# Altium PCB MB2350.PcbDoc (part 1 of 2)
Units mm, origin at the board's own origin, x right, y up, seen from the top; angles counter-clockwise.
Board outline 43 x 52.78 mm, 4 copper layers (Top Layer, Internal 1, Internal 2, Bottom Layer), stack 1.565 mm thick; 87 components, 78 nets, 331 pads, 863 vias.
Unrouted connection lines stored in the file: 482.
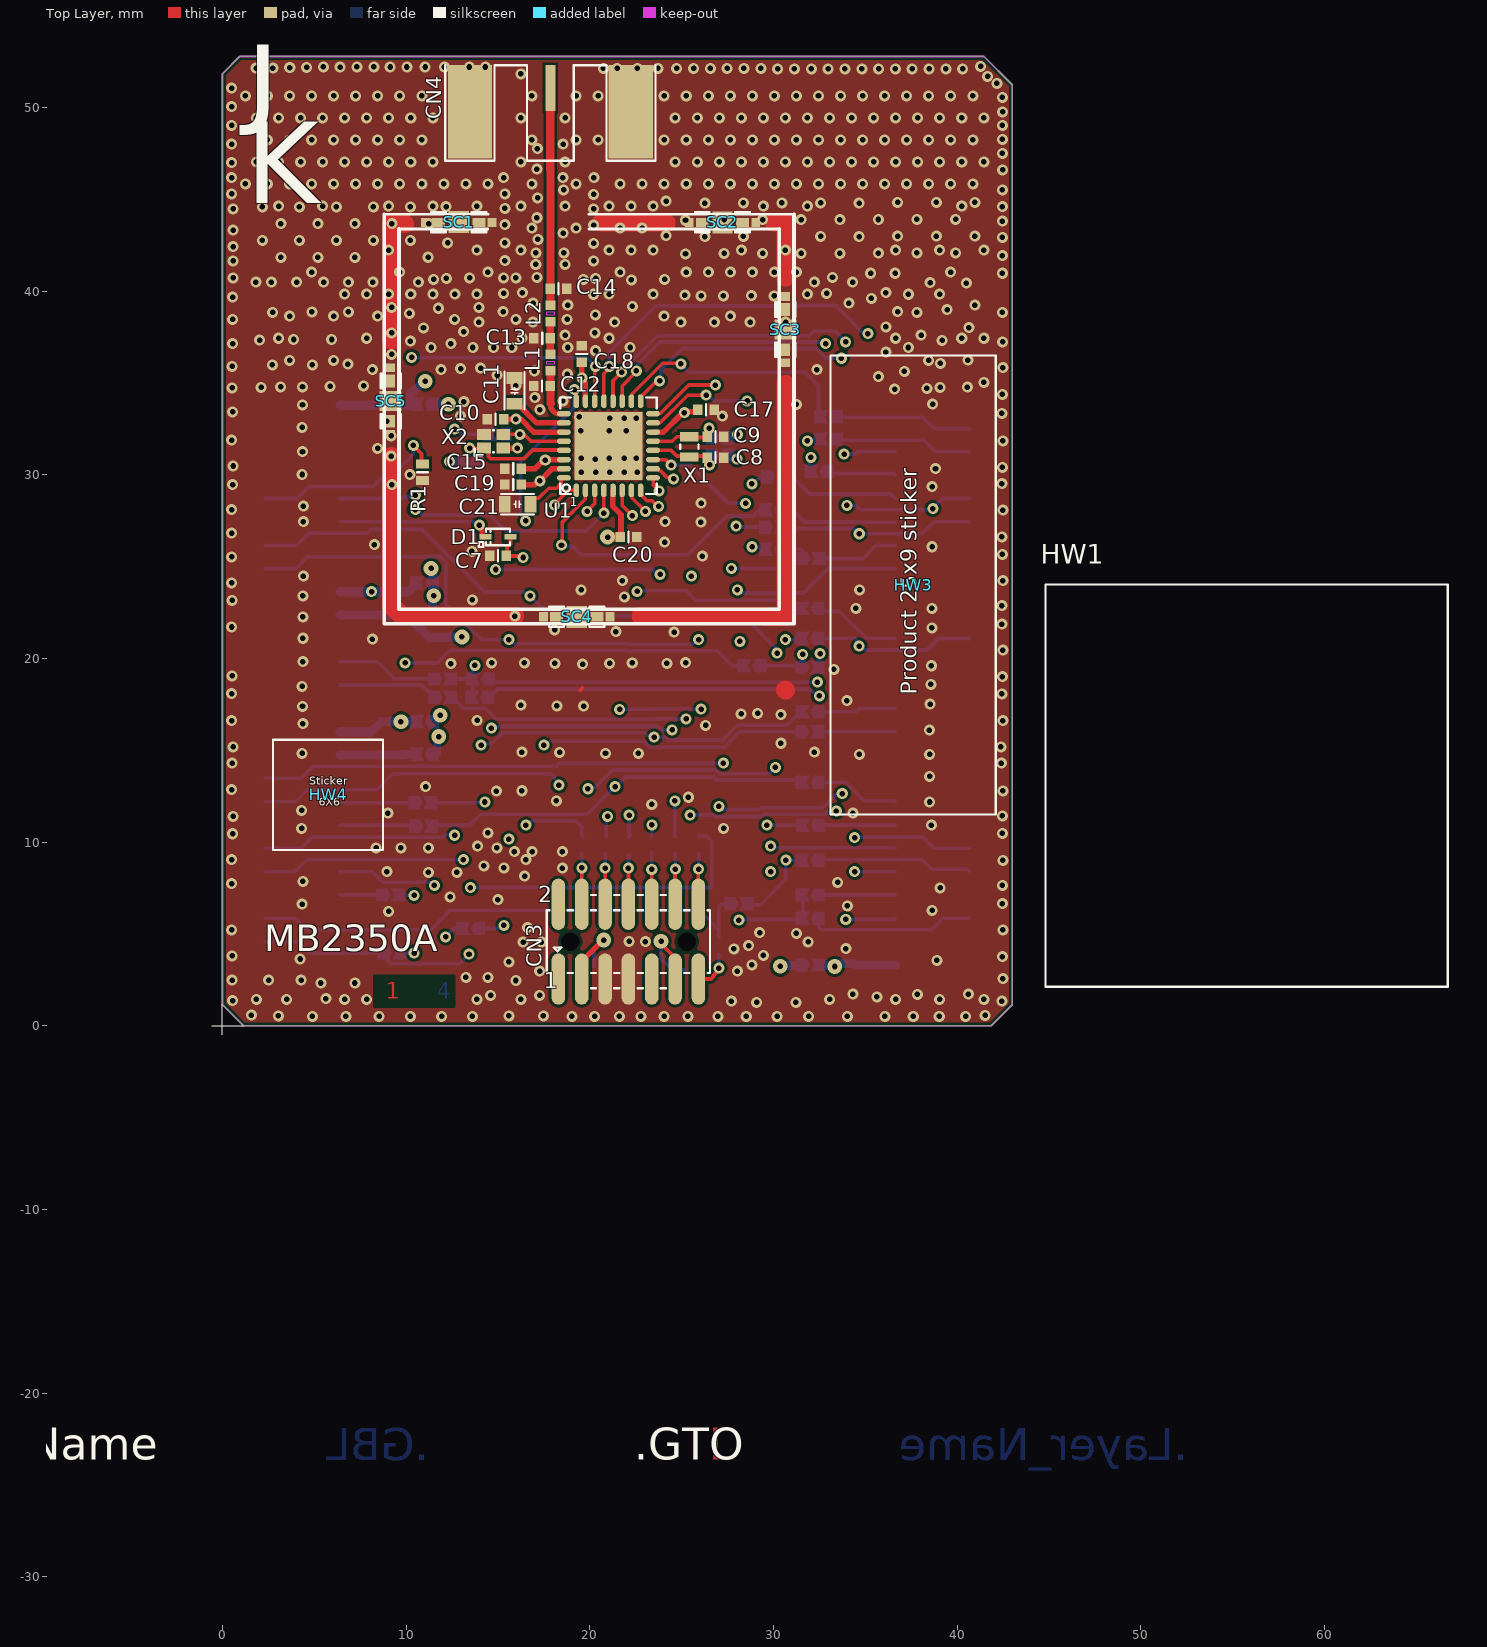
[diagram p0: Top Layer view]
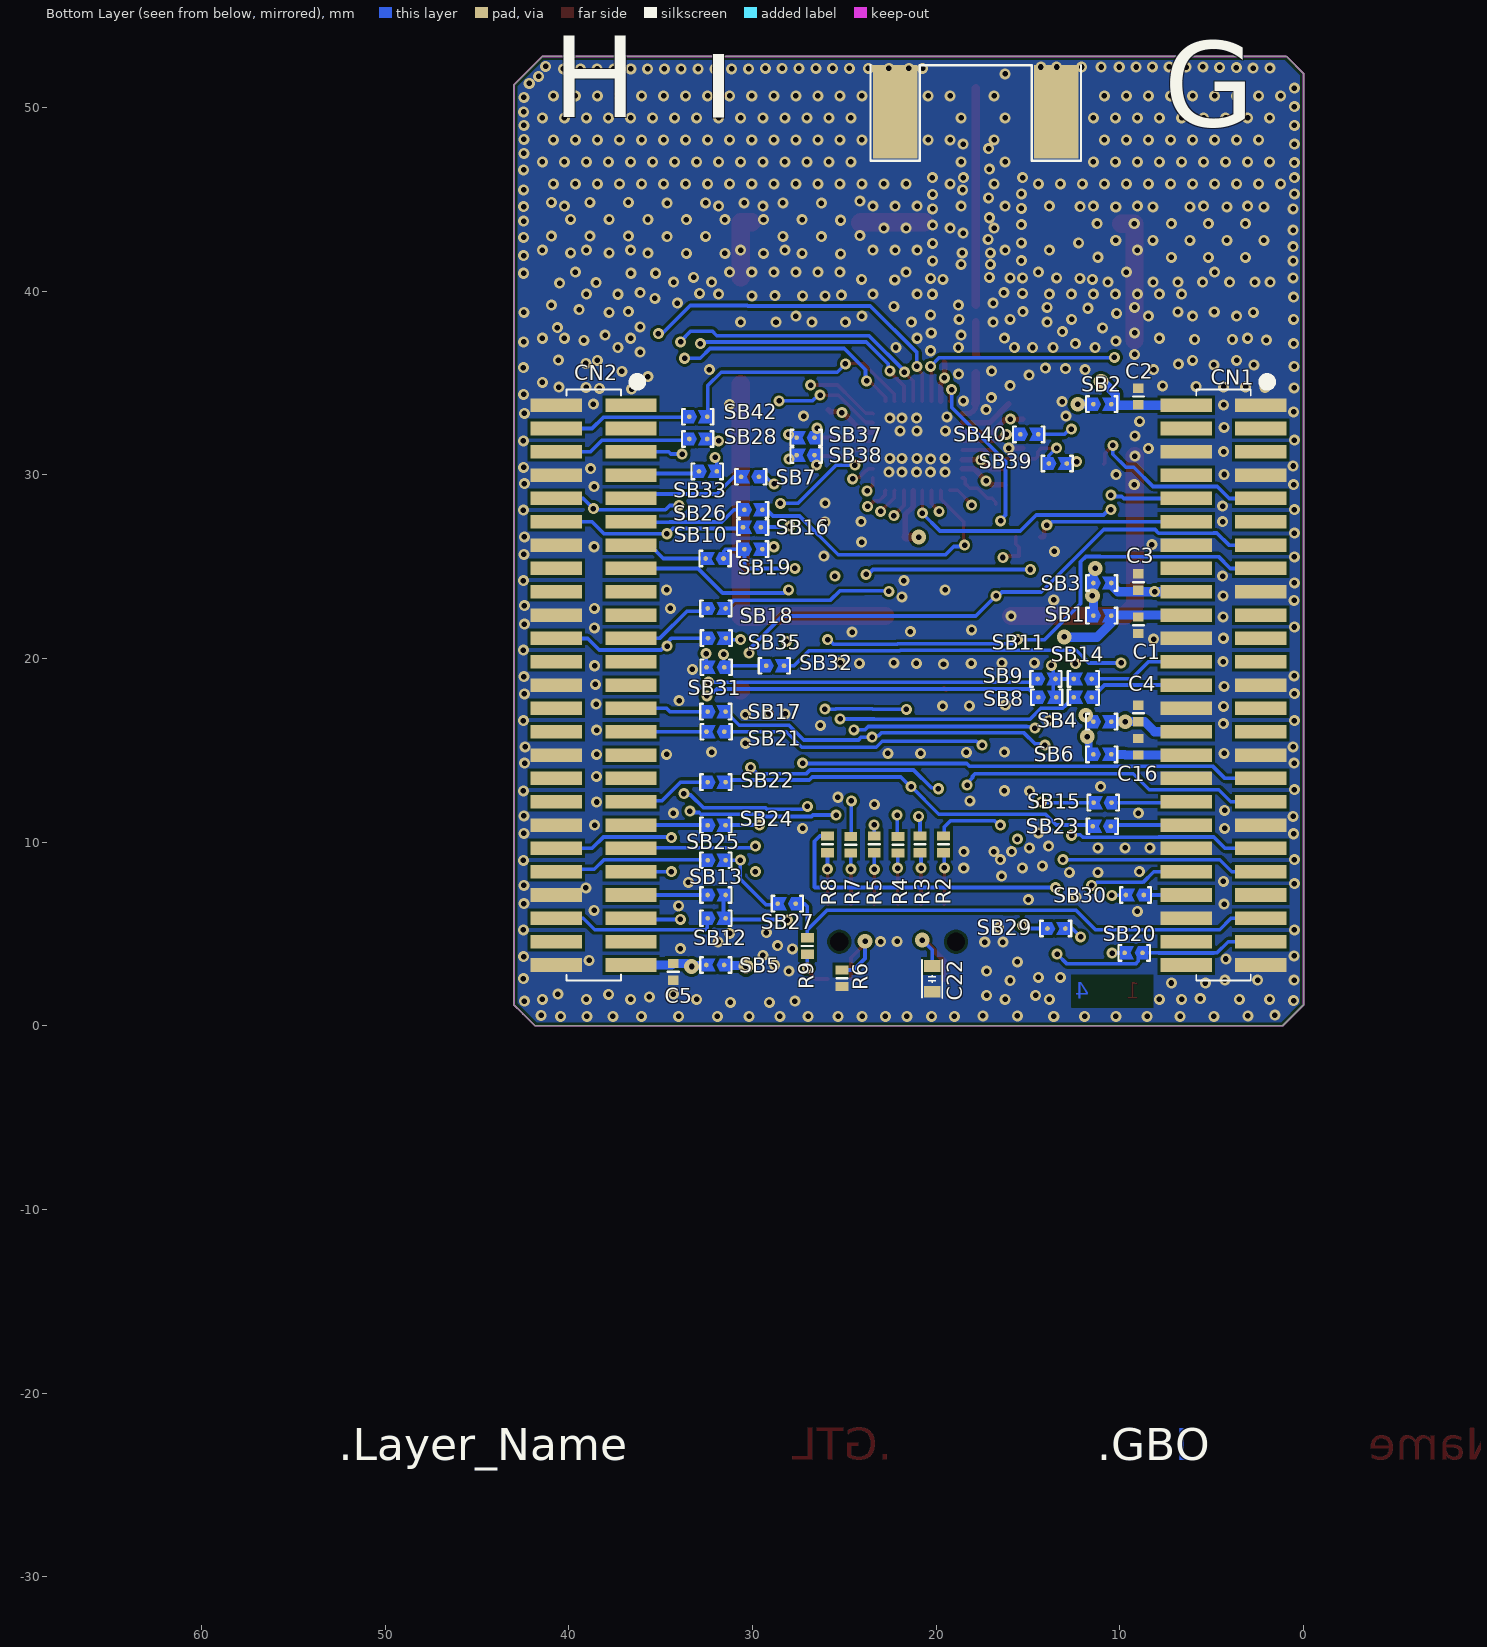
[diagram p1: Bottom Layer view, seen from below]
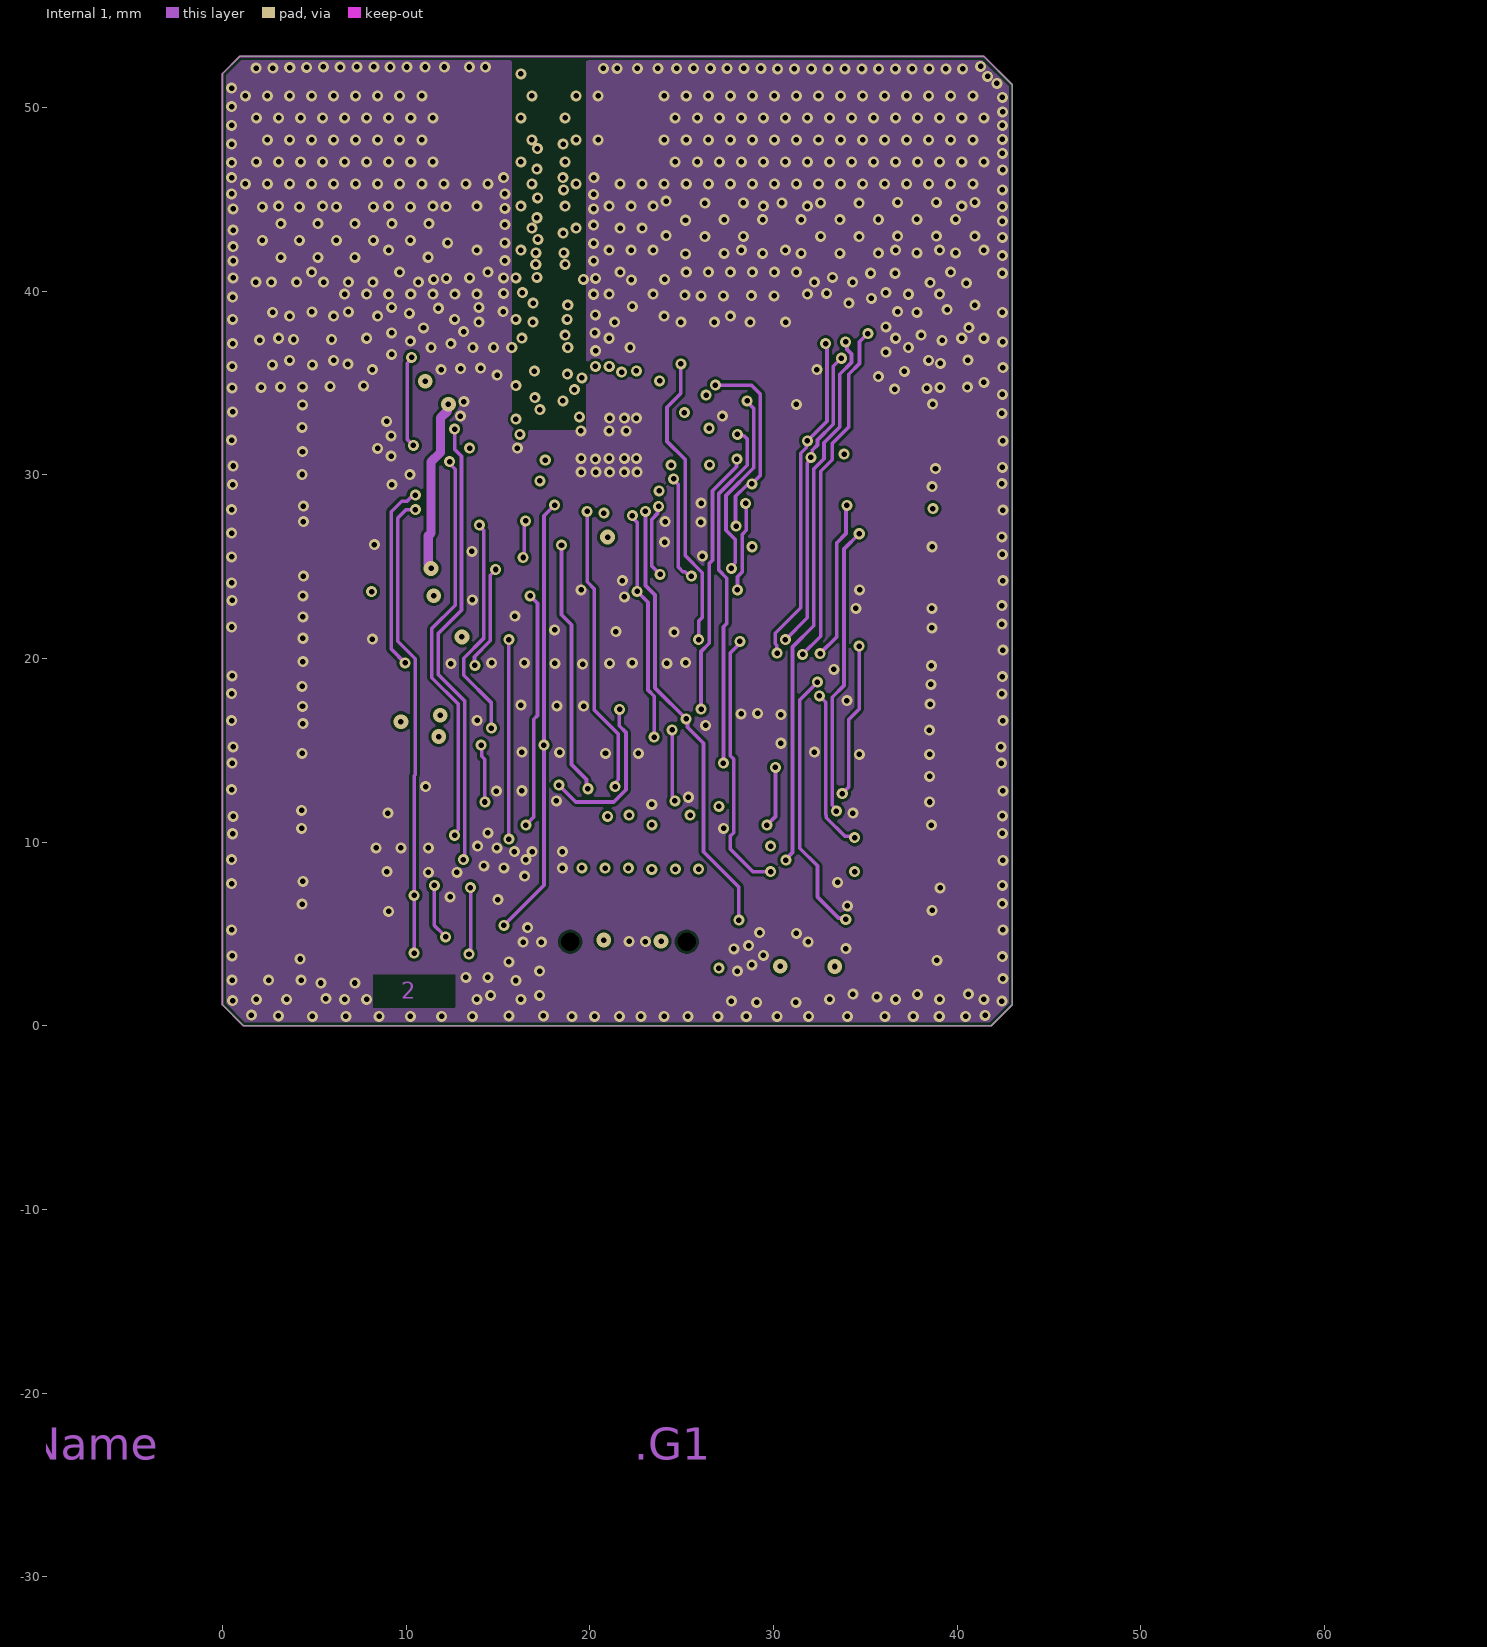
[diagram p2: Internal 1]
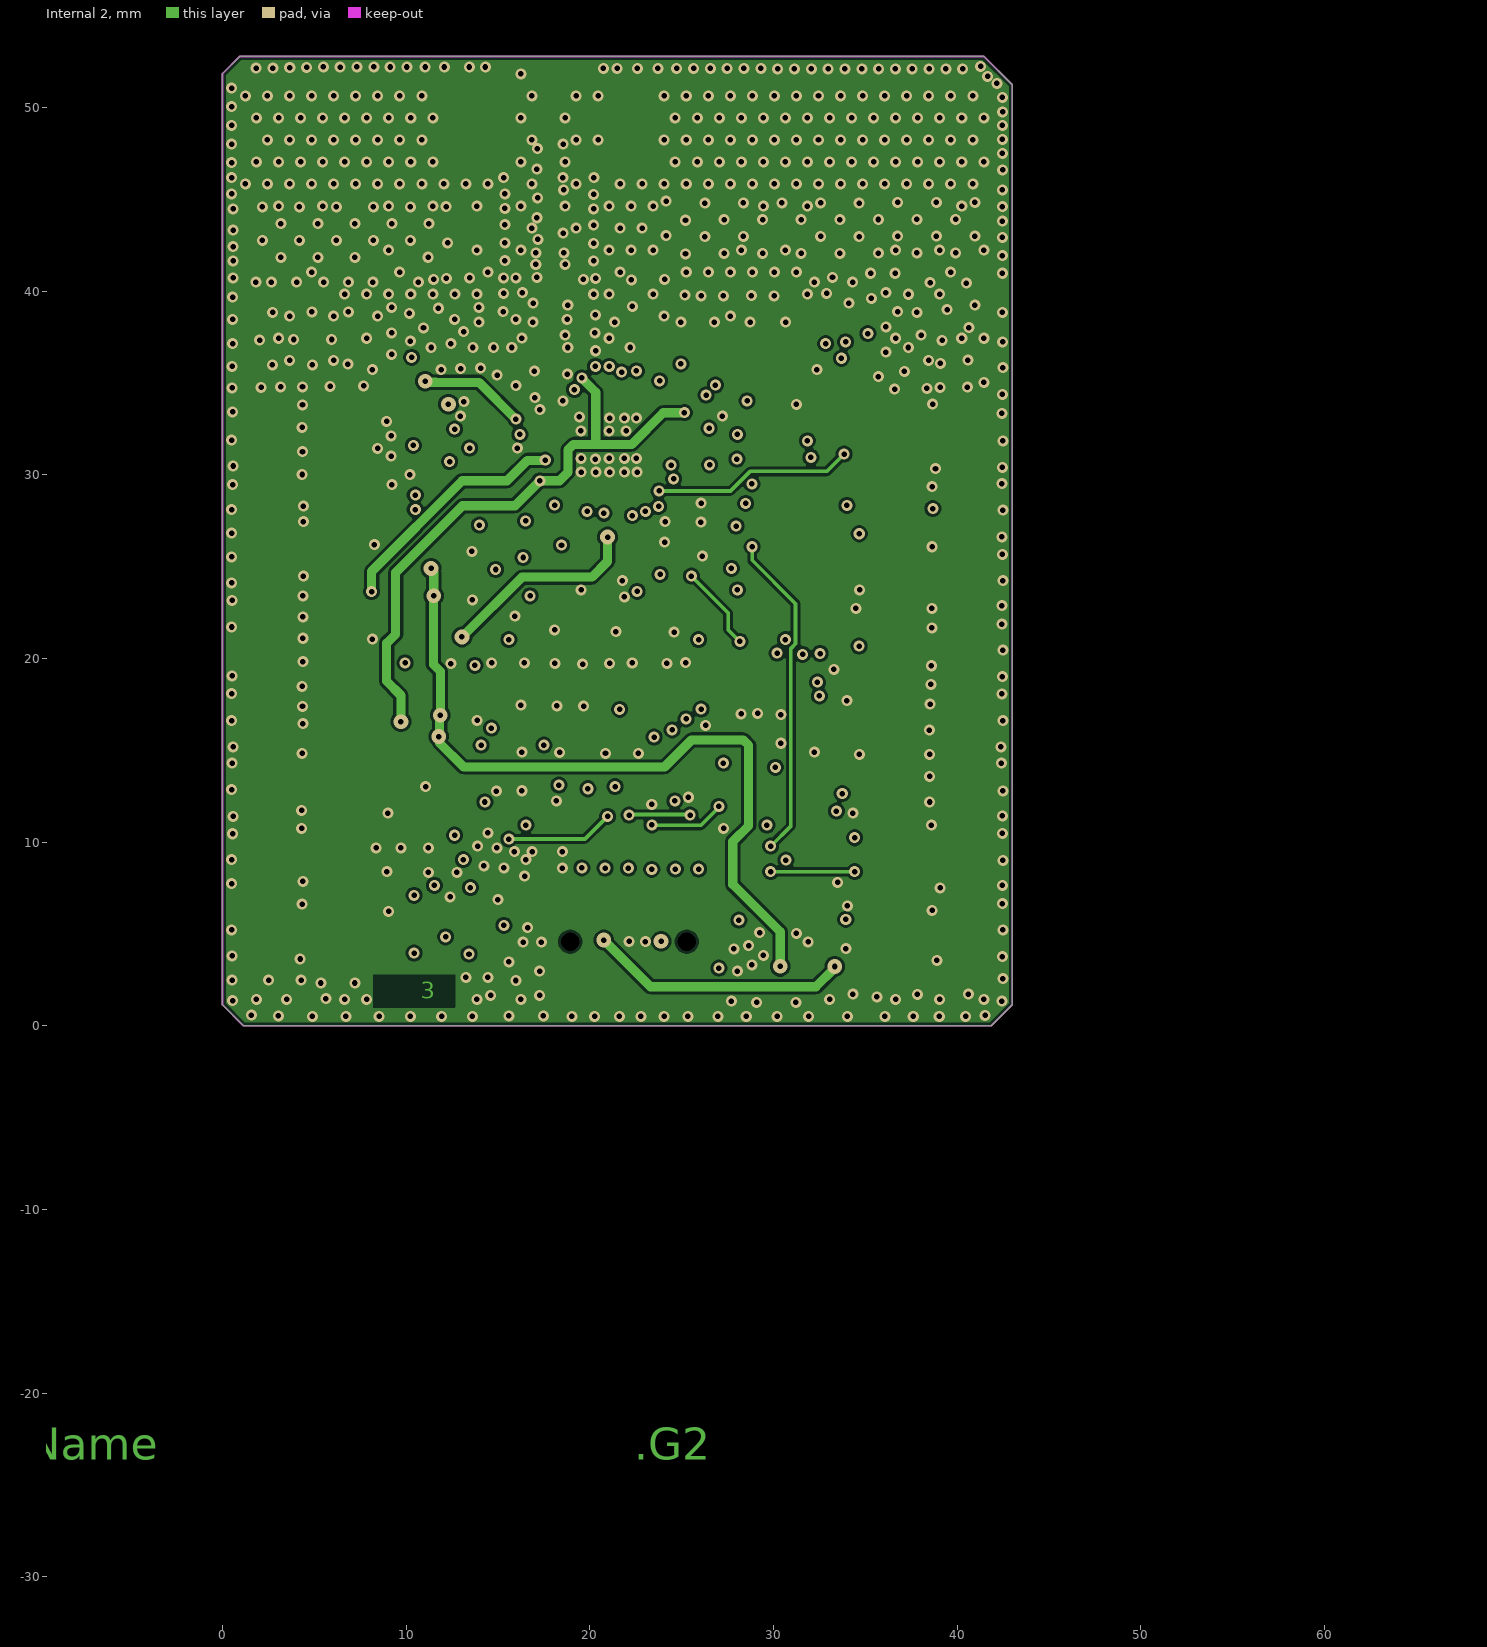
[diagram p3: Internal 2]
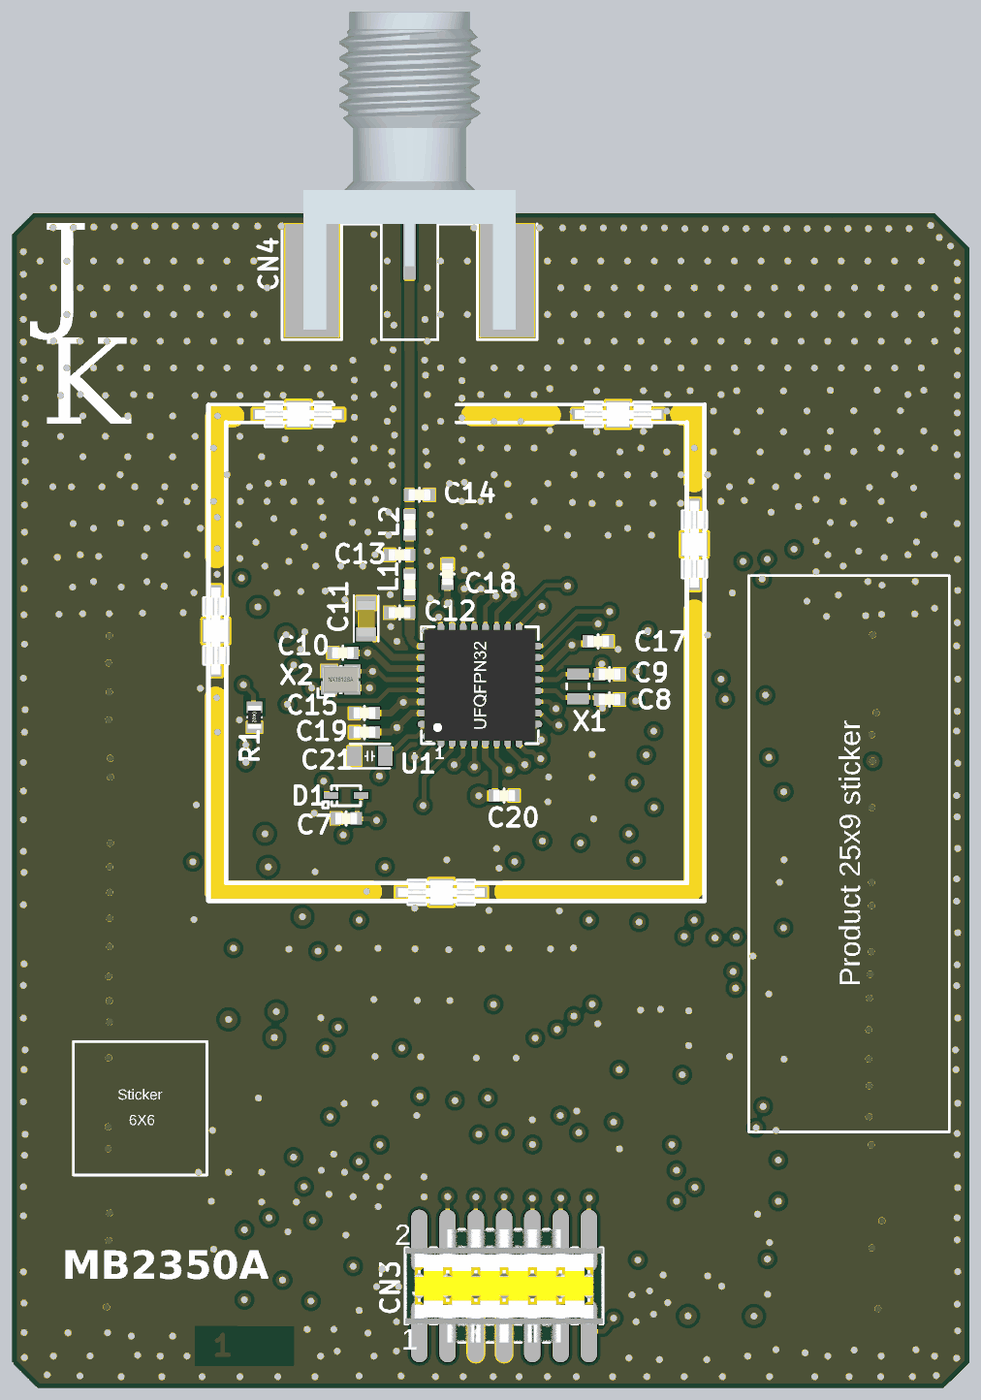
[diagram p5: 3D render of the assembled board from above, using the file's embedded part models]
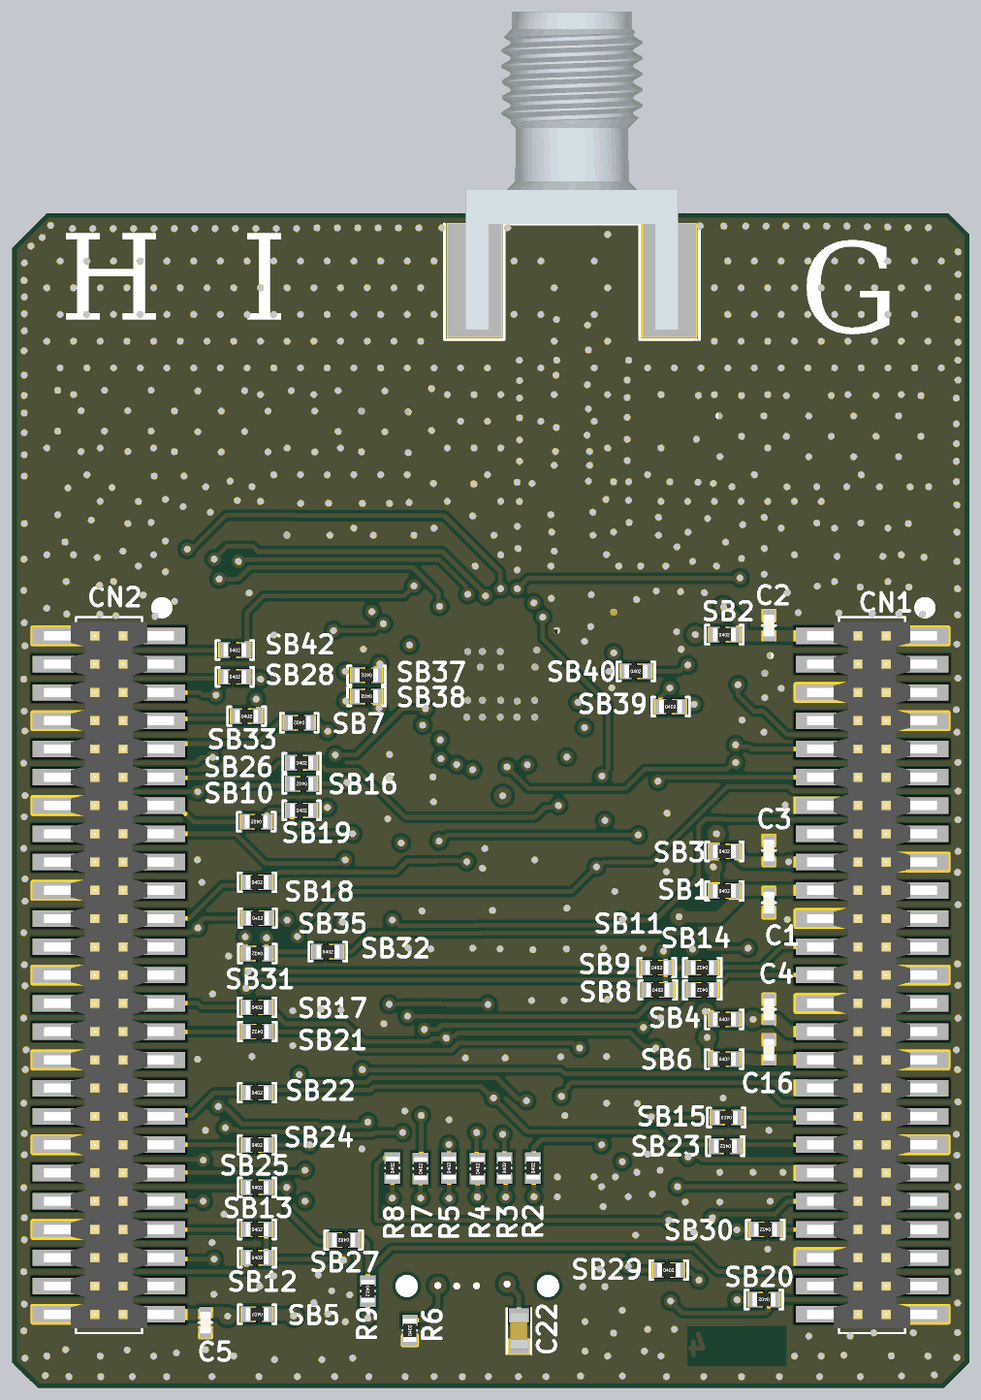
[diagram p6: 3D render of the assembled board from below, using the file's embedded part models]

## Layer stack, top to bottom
Top Solder: solder mask 0.0178, Solder Resist, Dk 4.2
Top Layer: signal copper 0.0406
Dielectric 1: core 0.0762, FR-4, Dk 3.7
Internal 1: signal copper 0.0305
Dielectric 3: prepreg 1.27, Dk 4.5
Internal 2: signal copper 0.0305
Dielectric 2: core 0.0762, Dk 3.7
Bottom Layer: signal copper 0.0406
Bottom Solder: solder mask 0.0178, Solder Resist, Dk 4.2

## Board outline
0,1.139 0,45.75 0,51.844 0.935,52.779 41.455,52.779 41.456,52.779 43,51.235 43,1.141 43.001,1.141 41.852,0 1.139,0

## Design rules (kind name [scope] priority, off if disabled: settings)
Clearance "RF Path 3" [InNet('NetC14_2')] p1: gap=0.13 ignorepadtopadclearanceinfootprint=FALSE
Clearance "RF Path 3_1" [InNet('NetC12_2')] p2: gap=0.13 ignorepadtopadclearanceinfootprint=FALSE
Clearance "RF Path 2" [InNet('NetC13_2')] p3: gap=0.13 ignorepadtopadclearanceinfootprint=FALSE
Clearance "RF Path 1" [InNet('ANT')] p4: gap=0.13 ignorepadtopadclearanceinfootprint=FALSE
Clearance [All] p5: gap=0.15 ignorepadtopadclearanceinfootprint=FALSE
ComponentClearance [All] p1: gap=0.2 collisioncheckmode=3 verticalgap=0.2 showdistances=FALSE
DiffPairsRouting [InDifferentialPairClass('DIFF90')] p1: maxlimit=0.254 minlimit=0.125 mostfreqgap=0.226 toplayer_maxgap=0.226 toplayer_minwidth=0.155 toplayer_maxwidth=0.155 toplayer_prefwidth=0.155 midlayer1_mingap=0.15 midlayer1_prefgap=0.15 midlayer1_minwidth=0.083 midlayer1_maxwidth=0.127 midlayer1_prefwidth=0.1 midlayer2_mingap=0.15 midlayer2_prefgap=0.15 midlayer2_minwidth=0.083 midlayer2_maxwidth=0.127 midlayer2_prefwidth=0.1 bottomlayer_mingap=0.15 bottomlayer_minwidth=0.155 bottomlayer_maxwidth=0.226 bottomlayer_prefwidth=0.155 maxuncoupledlength=12.7
HoleSize [All] p1: absolutevalues=TRUE maxlimit=10 minlimit=0.025 maxpercent=80.000 minpercent=20.000
MinimumSolderMaskSliver [All] p1: minsoldermaskwidth=0
PlaneConnect [All] p1: planeconnectstyle=Relief reliefexpansion=0.508 reliefentries=4 reliefconductorwidth=0.21 reliefairgap=0.21
PolygonConnect Path_RF [InNet('NetC12_2')] p1: connectstyle=Direct reliefconductorwidth=0.254 reliefentries=4 polygonreliefangle="90 Angle" airgapwidth=0.254
PolygonConnect PolygonConnect_via [IsVia] p2: connectstyle=Direct reliefconductorwidth=0.254 reliefentries=4 polygonreliefangle="90 Angle" airgapwidth=0.254
PolygonConnect General [All] p3: connectstyle=Direct reliefconductorwidth=0.2 reliefentries=4 polygonreliefangle="90 Angle" airgapwidth=0.2
RoutingVias [All] p1: holewidth=0.3 width=0.8 viastyle="Through Hole" minholewidth=0.2 minwidth=0.5 maxholewidth=3.5 maxwidth=6.5
SilkToSilkClearance [All] p1: silktosilkclearance=0.2
SilkToSolderMaskClearance [IsPad] p1: minsilkscreentomaskgap=0.2 clearancetoexposedcopper=TRUE
SolderMaskExpansion [All] p1: expansion=0.102 istentingtop=FALSE
Width [All] p1: maxlimit=6 minlimit=0.15 preferedwidth=0.254 toplayer_prefwidth=0.2 midlayer1_minwidth=0.2 midlayer1_maxwidth=0.512 midlayer2_minwidth=0.2 midlayer2_maxwidth=0.512 bottomlayer_prefwidth=0.2 minimp=50.000000 maximp=50.000000 favimp=50.000000
23 further rules are at their usual default settings.

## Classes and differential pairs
component class "STM32 microcontroller I/Os & Clock": C1 C2 C3 C4 C5 C7 C8 C9 C16 CN1 CN2 D1 R1 SB1 SB2 SB3 SB4 SB5 SB6 SB7 SB8 SB9 SB10 SB11 SB12 SB13 SB14 SB15 SB16 SB17 SB18 SB19 SB20 SB21 SB22 SB23 SB24 SB25 SB26 SB27 SB28 SB29 SB30 SB31 SB32 SB33 SB35 SB37 SB38 SB39 SB40 SB42 U1 X1 X2
component class "RF & Power Management Schematic": C10 C11 C12 C13 C14 C15 C17 C18 C19 C20 C21 C22 CN3 CN4 HW1 L1 L2 R2 R3 R4 R5 R6 R7 R8 R9 SC1 SC2 SC3 SC4 SC5
component class Project_Overview: HW2 HW3 HW4

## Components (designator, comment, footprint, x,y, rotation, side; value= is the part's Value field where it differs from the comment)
C1 "Capacitor" C0402 9,21.804 r90 bottom value=1uF
C2 "Capacitor" C0402 9,34.255 r270 bottom value=1uF
C3 "Capacitor" C0402 9,24.151 r270 bottom value=1uF
C4 "Capacitor" C0402 9,17.01 r270 bottom value=1uF
C5 "Capacitor" C0402 34.319,2.937 r90 bottom value=1uF
C7 "Capacitor" C0402 15.004,25.588 r0 top value=100nF
C8 "Capacitor" C0402 26.838,30.932 r180 top value=6pF
C9 "Capacitor" C0402 26.841,32.069 r180 top value=6pF
C10 "Capacitor" C0402 14.857,33.026 r180 top value=100nF
C11 "Capacitor" C0603 15.9,34.566 r270 top value=470nF
C12 "Capacitor" C0402 17.404,34.835 r0 top value=1.5pF
C13 "Capacitor" C0402 17.404,37.43 r0 top value=1.8pF
C14 "Capacitor" C0402 18.297,40.125 r180 top value=1pF
C15 "Capacitor" C0402 15.826,30.325 r180 top value=100nF
C16 "Capacitor" C0402 9,15.189 r270 bottom value=1uF
C17 "Capacitor" C0402 26.326,33.544 r0 top value=100nF
C18 "Capacitor" C0402 19.563,36.569 r90 top value=100nF
C19 "Capacitor" C0402 15.826,29.464 r180 top value=100nF
C20 "Capacitor" C0402 22.101,26.612 r180 top value=1uF
C21 "Capacitor" C0603_H0P8 16.067,28.393 r0 top value=4.7uF
C22 "Capacitor" C0603 20.231,2.554 r90 bottom value=1uF
CN1 "Header 25x2" FTSH-125-02-L-DV 4.366,18.548 r180 bottom locked
CN2 "Header 25x2" FTSH-125-02-L-DV 38.656,18.548 r180 bottom locked
CN3 "Header 7x2" CON_SAMTEC_FTSH-107-01-L-DV-K-A 22.101,4.579 r0 top locked
CN4 "SMA-J-P-H-ST-EM1" CON_SMA-RF_CINCH_142-0701-851 17.854,52.3 r0 top locked value=Jack_SMA_142-0701-851
D1 "SCHOTTKY_1A_2K" DIO_SOD523_1A_2K 15,26.612 r180 top value=BAT54KFILM
HW1 "Shield Cover" SHIELD_WURTH_36003200_21P8X21P8 55.763,13.069 r0 top value=36003200
HW3 "STICKER_PRODUCT" STICKER_PRODUCT_25X9 37.602,23.997 r90 top value="Sticker Product"
HW4 "STICKER_ES" STICKER_ES_6X6 5.746,12.567 r0 top value=N/A
L1 "Inductor" C0402 17.854,36.106 r90 top value=3.3nH
L2 "Inductor" C0402 17.854,38.786 r90 top value=3.3nH
R1 "Resistor" R0402 10.882,30.133 r270 top value=100K
R2 "Resistor" R0402 19.605,9.878 r90 bottom value=47R
R3 "Resistor" R0402 20.887,9.878 r90 bottom value=47R
R4 "Resistor" R0402 22.092,9.852 r90 bottom value=47R
R5 "Resistor" R0402 23.376,9.878 r90 bottom value=47R
R6 "Resistor" R0402 25.133,2.587 r90 bottom value=47R
R7 "Resistor" R0402 24.658,9.853 r90 bottom value=47R
R8 "Resistor" R0402 25.922,9.878 r90 bottom value=47R
R9 "Resistor" R0402 27.024,4.35 r270 bottom value=47R
SB1 "SB_ON" SOLDER-BRIDGE_R0402-0R 11,22.329 r180 bottom
SB2 "SB_ON" SOLDER-BRIDGE_R0402-0R 11,33.846 r180 bottom
SB3 "SB_ON" SOLDER-BRIDGE_R0402-0R 11,24.106 r180 bottom
SB4 "SB_ON" SOLDER-BRIDGE_R0402-0R 11,16.56 r180 bottom
SB5 "SB_ON" SOLDER-BRIDGE_R0402-0R 32,3.308 r0 bottom
SB6 "SB_ON" SOLDER-BRIDGE_R0402-0R 11,14.773 r180 bottom
SB7 "SB_ON" SOLDER-BRIDGE_R0402-0R 30.107,29.887 r0 bottom
SB8 "SB_ON" SOLDER-BRIDGE_R0402-0R 13.995,17.882 r180 bottom
SB9 "SB_ON" SOLDER-BRIDGE_R0402-0R 14.036,18.883 r180 bottom
SB10 "SB_ON" SOLDER-BRIDGE_R0402-0R 32.038,25.439 r0 bottom
SB11 "SB_ON" SOLDER-BRIDGE_R0402-0R 11.991,18.883 r0 bottom
SB12 "SB_ON" SOLDER-BRIDGE_R0402-0R 32,5.848 r180 bottom
SB13 "SB_ON" SOLDER-BRIDGE_R0402-0R 32,7.118 r180 bottom
SB14 "SB_ON" SOLDER-BRIDGE_R0402-0R 11.991,17.882 r0 bottom
SB15 "SB_ON" SOLDER-BRIDGE_R0402-0R 10.912,12.15 r0 bottom
SB16 "SB_ON" SOLDER-BRIDGE_R0402-0R 30,27.141 r0 bottom
SB17 "SB_ON" SOLDER-BRIDGE_R0402-0R 32,17.102 r180 bottom
SB18 "SB_ON" SOLDER-BRIDGE_R0402-0R 32,22.721 r180 bottom
SB19 "SB_ON" SOLDER-BRIDGE_R0402-0R 30,25.952 r180 bottom
SB20 "SB_ON" SOLDER-BRIDGE_R0402-0R 9.224,3.969 r0 bottom
SB21 "SB_ON" SOLDER-BRIDGE_R0402-0R 31.988,16.008 r0 bottom
SB22 "SB_ON" SOLDER-BRIDGE_R0402-0R 32,13.264 r180 bottom
SB23 "SB_ON" SOLDER-BRIDGE_R0402-0R 10.955,10.86 r0 bottom
SB24 "SB_ON" SOLDER-BRIDGE_R0402-0R 32.001,10.916 r180 bottom
SB25 "SB_ON" SOLDER-BRIDGE_R0402-0R 32,9.012 r180 bottom
SB26 "SB_ON" SOLDER-BRIDGE_R0402-0R 30,28.09 r180 bottom
SB27 "SB_ON" SOLDER-BRIDGE_R0402-0R 28.113,6.648 r0 bottom
SB28 "SB_ON" SOLDER-BRIDGE_R0402-0R 33,31.948 r180 bottom
SB29 "SB_ON" SOLDER-BRIDGE_R0402-0R 13.5,5.293 r180 bottom
SB30 "SB_ON" SOLDER-BRIDGE_R0402-0R 9.158,7.118 r0 bottom
SB31 "SB_ON" SOLDER-BRIDGE_R0402-0R 31.988,19.517 r0 bottom
SB32 "SB_ON" SOLDER-BRIDGE_R0402-0R 28.819,19.6 r180 bottom
SB33 "SB_ON" SOLDER-BRIDGE_R0402-0R 32.473,30.183 r180 bottom
SB35 "SB_ON" SOLDER-BRIDGE_R0402-0R 31.981,21.105 r180 bottom
SB37 "SB_ON" SOLDER-BRIDGE_R0402-0R 27.084,32.023 r0 bottom
SB38 "SB_ON" SOLDER-BRIDGE_R0402-0R 27.084,31.069 r0 bottom
SB39 "SB_ON" SOLDER-BRIDGE_R0402-0R 13.421,30.611 r180 bottom
SB40 "SB_ON" SOLDER-BRIDGE_R0402-0R 14.974,32.198 r180 bottom
SB42 "SB_ON" SOLDER-BRIDGE_R0402-0R 33,33.153 r180 bottom
SC1 "Shield-clip_S0951-46R" CLIP_HARWIN_S0951-46R#1 12.862,43.742 r180 top locked value=S0951-46R
SC2 "Shield-clip_S0951-46R" CLIP_HARWIN_S0951-46R#2 27.222,43.742 r180 top locked value=S0951-46R
SC3 "Shield-clip_S0951-46R" CLIP_HARWIN_S0951-46R#2 30.65,37.903 r90 top locked value=S0951-46R
SC4 "Shield-clip_S0951-46R" CLIP_HARWIN_S0951-46R#2 19.283,22.267 r180 top locked value=S0951-46R
SC5 "Shield-clip_S0951-46R" CLIP_HARWIN_S0951-46R#2 9.15,34.013 r90 top value=S0951-46R
U1 "IC_STM32WBA23KEU7" ICC_UFQFPN32-EPAD_5X5_P050 21.014,31.575 r0 top locked value=STM32WBA23KEU7
X1 "XTAL_2_PINS" CRY_NX1610SE_2P 25.421,31.523 r270 top value=32.768kHz
X2 "XTAL_4_PINS" CRY_NX1612SA_4P 14.761,31.825 r0 top value=32MHz

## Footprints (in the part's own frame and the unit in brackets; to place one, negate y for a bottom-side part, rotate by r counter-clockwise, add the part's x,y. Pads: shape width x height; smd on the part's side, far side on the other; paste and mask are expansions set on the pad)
C0402 [mm]
  rect 0.51x0.56 smd mask+0.05: 1(-0.45,0) 2(0.45,0)
  silkscreen extent 0,-0.3 0,0.3, body extent -0.5,-0.3 0.5,0.3, height 0.4
C0603 [mm]
  rect 0.64x0.89 smd mask+0.05: 1(-0.7,0) 2(0.7,0)
  silkscreen extent -1.05,-0.55 1.02,0.55, body extent -0.9,-0.5 0.9,0.5, height 1.4
C0603_H0P8 [mm] "MCD-01540"
  rect 0.64x0.89 smd mask+0.05: 1(-0.7,0) 2(0.7,0)
  silkscreen extent -0.9,-0.55 0.9,0.55, body extent -0.9,-0.5 0.9,0.5, height 1
CLIP_HARWIN_S0951-46R#1 [mm] "MCD-01587_CLIP-X1"
  rect 0.48x0.5 smd mask+0.1: 1(-1.81,0) 1(1.81,0)
  rect 0.7x0.5 smd mask+0.1: 1(-1.1,0) 1(1.1,0)
  rect 1.1x1.2 smd mask+0.1: 1(0,-0.013)
  silkscreen extent -1.5,-0.55 1.5,0.55, body extent -2.05,-0.65 2.05,0.65, height 1.28
CLIP_HARWIN_S0951-46R#2 [mm] "MCD-01587_CLIP-X1"
  rect 0.48x0.5 smd mask+0.1: 1(-1.81,0) 1(1.81,0)
  rect 0.7x0.5 smd mask+0.1: 1(-1.1,0) 1(1.1,0)
  rect 1.1x1.2 smd mask+0.1: 1(0,0)
  silkscreen extent -1.5,-0.55 1.5,0.55, body extent -2.05,-0.65 2.05,0.65, height 1.28
CON_SAMTEC_FTSH-107-01-L-DV-K-A [mm] "MCD-01959"
  oval 0.74x2.79 smd mask+0.05: 1(-3.81,-2.035) 2(-3.81,2.035) 3(-2.54,-2.035) 4(-2.54,2.035) 5(-1.27,-2.035) 6(-1.27,2.035) 7(0,-2.035) 8(0,2.035) 9(1.27,-2.035) 10(1.27,2.035) 11(2.54,-2.035) 12(2.54,2.035) 13(3.81,-2.035) 14(3.81,2.035)
  round 0 hole 1 unplated paste-10 mask+0.05: NPTH1(-3.175,0) NPTH2(3.175,0)
  silkscreen extent -4.44,-2.54 4.44,2.54, body extent -4.44,-2.92 4.45,2.92, height 6.12
CON_SMA-RF_CINCH_142-0701-851 [mil] "MCD-02072"
  rect 21.65x98.43 smd mask+1.97: 1(0,-49.21)
  rect 95x200 smd mask+1.97: 2(172.48,-100) 3(-172.48,-100)
  rect 95x200 smd far side mask+1.97: 4(-172.48,-100) 5(172.48,-100)
  silkscreen extent -225,-205 225,0, body extent -189,-187 189,376, height 161
CRY_NX1610SE_2P [mm] "MCD-02291"
  rect 0.5x1 smd mask+0.05: 1(-0.55,0) 2(0.55,0)
  silkscreen extent -0.13,-0.5 0.13,0.5, body extent -0.8,-0.5 0.8,0.5, height 0.45
CRY_NX1612SA_4P [mm] "MCD-02262"
  rect 0.75x0.6 smd mask+0.038: 1(-0.525,-0.375) 2(0.525,-0.375) 3(0.525,0.375) 4(-0.525,0.375)
  silkscreen extent -1.02,-0.8 0.03,0.6, body extent -0.8,-0.6 0.8,0.6, height 0.51
DIO_SOD523_1A_2K [mm] "MCD-01677"
  rect 0.65x0.3 smd mask+0.05: 1(-0.675,0) 2(0.675,0)
  silkscreen extent -0.65,-0.45 1.05,0.55, body extent -0.85,-0.45 0.85,0.45, height 0.71
FTSH-125-02-L-DV [mil] "Header2x25 Reverse 1.27mm SAMTEC (FTSH-125-02-L-DV)"
  rect 110x29.02 smd: 1(80,600) 2(-80,600) 3(80,550) 4(-80,550) 5(80,500) 6(-80,500) 7(80,450) 8(-80,450) 9(80,400) 10(-80,400) 11(80,350) 12(-80,350) 13(80,300) 14(-80,300) 15(80,250) 16(-80,250) 17(80,200) 18(-80,200) 19(80,150) 20(-80,150) 21(80,100) 22(-80,100) 23(80,50) 24(-80,50) 25(80,0) 26(-80,0) 27(80,-50) 28(-80,-50) 29(80,-100) 30(-80,-100) 31(80,-150) 32(-80,-150) 33(80,-200) 34(-80,-200) 35(80,-250) 36(-80,-250) 37(80,-300) 38(-80,-300) 39(80,-350) 40(-80,-350) 41(80,-400) 42(-80,-400) 43(80,-450) 44(-80,-450) 45(80,-500) 46(-80,-500) 47(80,-550) 48(-80,-550) 49(80,-600) 50(-80,-600)
  silkscreen extent -58,-633 103,659, body extent -115,-625 115,625, height 190
ICC_UFQFPN32-EPAD_5X5_P050 [mm] "MCD-01398"
  oval 0.3x0.75 smd mask+0.05: 1(-1.75,-2.425) 2(-1.25,-2.425) 3(-0.75,-2.425) 4(-0.25,-2.425) 5(0.25,-2.425) 6(0.75,-2.425) 7(1.25,-2.425) 8(1.75,-2.425) 17(1.75,2.425) 18(1.25,2.425) 19(0.75,2.425) 20(0.25,2.425) 21(-0.25,2.425) 22(-0.75,2.425) 23(-1.25,2.425) 24(-1.75,2.425)
  oval 0.75x0.3 smd mask+0.05: 9(2.425,-1.75) 10(2.425,-1.25) 11(2.425,-0.75) 12(2.425,-0.25) 13(2.425,0.25) 14(2.425,0.75) 15(2.425,1.25) 16(2.425,1.75) 25(-2.425,1.75) 26(-2.425,1.25) 27(-2.425,0.75) 28(-2.425,0.25) 29(-2.425,-0.25) 30(-2.425,-0.75) 31(-2.425,-1.25) 32(-2.425,-1.75)
  rect 3.7x3.7 smd mask+0.05: 33(0,0)
  silkscreen extent -2.63,-2.63 2.63,2.63, body extent -2.55,-2.55 2.55,2.55, height 0.6
R0402 [mm]
  rect 0.51x0.7 smd mask+0.05: 1(-0.45,0) 2(0.45,0)
  silkscreen extent 0,-0.3 0,0.3, body extent -0.52,-0.3 0.52,0.3, height 0.4
SHIELD_WURTH_36003200_21P8X21P8 [mm] "MCD-04686"
  silkscreen extent -10.95,-10.95 10.95,10.95, body extent -10.9,-10.9 10.9,10.9, height 0.3
SOLDER-BRIDGE_R0402-0R [mil] "MCD-01619"
  round 10 smd paste-393.7: 1(-17.72,0) 2(20.67,0)
  Top Layer region: -30.51,-13.78 -30.51,13.78 -8.37,13.78 -1.48,0 -8.37,-13.78
  Top Layer region: 1.48,13.78 8.37,0 1.48,-13.78 30.51,-13.78 30.51,13.78
  silkscreen extent -33,-17 33,17, body extent -20,-12 20,12, height 14
STICKER_ES_6X6 [mm] "Sticker to mention board QR code 8X8"
  silkscreen extent -3,-3 3,3
STICKER_PRODUCT_25X9 [mm] "Sticker to mention board CPN code"
  silkscreen extent -12.5,-4.5 12.5,4.5

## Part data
C1 C2 C3 C4 C5 C16 C20: library part MCD-01722, "Capacitor, MLCC, 1uF, 10V, X5R, +/-10%, 0402, T=0.5mm", Manufacturer=YAGEO, Manufacturer_Part_Number=CC0402KRX5R6BB105, Package=0402
C7 C10 C15 C17 C18 C19: library part MCD-00006, "Capacitor, MLCC, 100nF, 16V, X7R, +/-10%, 0402, T=0.5mm", Alternate_Manufacturer=MURATA, Alternate_Manufacturer_Part_Number=GCM155R71C104KA55D, Manufacturer=YAGEO, Manufacturer_Part_Number=CC0402KRX7R7BB104, Package=C0402
C8 C9: library part MCD-03185, "Capacitor, MLCC, 6pF, 50V, C0G/NP0, +/-0,25pF, 0402, T=0.5mm", Manufacturer=MURATA, Manufacturer_Part_Number=GJM1555C1H6R0CB01, Package=0402
C11: library part MCD-01006, "Capacitor, MLCC, 470nF, 16V, X7R, +/-10%, 0603, T=0.8mm", Manufacturer=YAGEO, Manufacturer_Part_Number=CC0603KRX7R7BB474, Package=0603
C12: library part MCD-02994, "Capacitor, MLCC, 1.5pF, 50V, C0G, +/-0.25pF, 0402, T=0.5mm", Manufacturer=MURATA, Manufacturer_Part_Number=GRM1555C1H1R5CA01, Package=0402
C13: library part MCD-02995, "Capacitor, MLCC, 1.8pF, 50V, C0G, +/-0.25pF, 0402, T=0.5mm", Manufacturer=MURATA, Manufacturer_Part_Number=GRM1555C1H1R8CA01, Package=0402
C14: library part MCD-03045, "Capacitor, MLCC, 1.0pF, 50V, C0G, +/-0.25pF, 0402, T=0.5mm", Manufacturer=MURATA, Manufacturer_Part_Number=GRM1555C1H1R0CA01, Package=0402
C21: library part MCD-01721, "Capacitor, MLCC, 4.7uF, 10V, X5R, +/-10%, 0603, T=0.8mm", Manufacturer=YAGEO, Manufacturer_Part_Number=CC0603KRX5R6BB475, Package=0603
C22: library part MCD-00010, "Capacitor, MLCC, 1uF, 16V, X5R, 10%, 0603, T=0,8mm", Manufacturer=YAGEO, Manufacturer_Part_Number=CC0603KRX5R7BB105, Package=C0603
CN1 CN2: library part MCD-02746, "Header, 25x2, 1.27mm, VR, SMD, T=4.83mm", Manufacturer=SAMTEC, Manufacturer_Part_Number=FTSH-125-02-L-DV
CN3: library part MCD-01531, "Header, 7x2, 1.27mm, VR, T=5.97mm, FTSH series STDC14 without Alignment Pin", Manufacturer=SAMTEC, Manufacturer_Part_Number=FTSH-107-01-L-DV-K
CN4: library part MCD-02072, "Jack_SMA, VR, PCB edge, 50R, T=7.92mm", Alternate_Manufacturer=N/A, Manufacturer=JOHNSON, Manufacturer_Part_Number=142-0701-851
D1: library part MCD-01677, "Small signal Schottky diodes", Manufacturer=STMICROELECTRONICS, Manufacturer_HQ_COO=EU, Manufacturer_Part_Number=BAT54KFILM, Package=SOD-523
HW1: library part MCD-04686, "RF Shield cover, 21.5x21.5x3.3mm", Manufacturer="WURTH ELEKTRONIK", Manufacturer_Part_Number=36003200
HW3: library part MCD-00547, "Sticker product, 25x9mm", Manufacturer=N/A, Manufacturer_HQ_COO=Unknown
HW4: library part MCD-00234, "Sticker ES, 6x6mm", Manufacturer=N/A
L1 L2: library part MCD-03001, "Inductor, 3.3nH, +/-0.3nH, 800 mA, 0.125Ohm, 0402, T=0.5mm", Manufacturer=MURATA, Manufacturer_Part_Number=LQG15HS3N3S02, Package=0402
R1: library part MCD-00059, "Resistor, 100K, 0402, +/-1%, 1/16W", Manufacturer=YAGEO, Manufacturer_Part_Number=RC0402FR-07100KL, Package=0402
R2 R3 R4 R5 R6 R7 R8 R9: library part MCD-00481, "Resistor,47R,0402,1%,1/16W", Manufacturer=YAGEO, Manufacturer_Part_Number=RC0402FR-0747RL, Package=R0402
SB1 SB2 SB3 SB4 SB5 SB6 SB7 SB8 SB9 SB10 SB11 SB12 SB13 SB14 SB15 SB16 SB17 SB18 SB19 SB20 SB21 SB22 SB23 SB24 SB25 SB26 SB27 SB28 SB29 SB30 SB31 SB32 SB33 SB35 SB37 SB38 SB39 SB40 SB42: library part MCD-01618, "Solder Bridge 0402 ON", Manufacturer=YAGEO, Manufacturer_Part_Number=RC0402JR-070RL, Package=SB0402
SC1 SC2 SC3 SC4 SC5: library part MCD-01587, "shield clip Harwin S0951-46R to fix RF shielded cavity", Manufacturer=HARWIN, Manufacturer_Part_Number=S0951-46R
U1: library part MCD-04382, "MCU, ARM Cortex-M33 32-bit, 512KB Flash, 96KB RAM, Crypto", Manufacturer=STMICROELECTRONICS, Manufacturer_Part_Number=STM32WBA23KEU7, Package=UFQFPN32
X1: library part MCD-02579, "Crystal, 32.768kHz, 6pF, +/-20ppm, 70KR, 1.6x1mm", Manufacturer=NDK, Manufacturer_Part_Number=NX1610SE-32.768KHZ-EXS00A-MU01501, Package=1.6x1mm
X2: library part MCD-02578, "Crystal, 32MHz, 8pF, +/-10ppm, 40R, 1612(metric), T=0.3mm", Manufacturer=NDK, Manufacturer_Part_Number=NX1612SA-32MHZ-EXS00A-CS09166, Package=1612(metric)

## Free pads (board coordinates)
  round 0.508 on Mech16: 1(-7.593,-30.556) 1(41.254,-30.556)

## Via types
v1: diameter 0.6, hole 0.3, Top Layer to Bottom Layer, tented both sides, 850 vias
v2: diameter 0.8, hole 0.3, Top Layer to Bottom Layer, tented both sides, 13 vias

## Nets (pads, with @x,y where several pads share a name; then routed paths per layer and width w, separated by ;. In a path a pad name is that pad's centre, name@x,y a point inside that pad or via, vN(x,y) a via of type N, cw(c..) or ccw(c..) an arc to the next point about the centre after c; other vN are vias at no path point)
GND: C1.1 C2.1 C3.1 C4.1 C5.1 C7.1 C8.1 C9.1 C10.2 C11.1 C12.1 C13.1 C14.1 C15.2 C16.1 C17.2 C18.2 C19.2 C20.1 C21.1 C22.1 CN1.1 CN1.6 CN1.7 CN1.14 CN1.17 CN1.22 CN1.25 CN1.28 CN1.31 CN1.34 CN1.37 CN1.40 CN1.46 CN1.49 CN2.2 CN2.8 CN2.14 CN2.20 CN2.26 CN2.32 CN2.38 CN2.44 CN2.50 CN3.5 CN3.7 CN4.2 CN4.3 CN4.4 CN4.5 R1.2 R6.1 SC1.1 SC2.1 SC3.1 SC4.1 SC5.1 U1.33 X2.2 X2.4 | length 50.8
  Top Layer w0.2: 19.467,18.267 19.585,18.385
  Top Layer w0.3: X2.2@15.286,31.45 v1(16.057,31.45)
  Top Layer w1: v1@9.203,31.013 9.203,29.464 9.203,27.509 9.185,27.491 9.185,22.892 9.77,22.306 v1(15.926,22.306) ; 9.21,37.324 v1(9.21,39.116) v1@9.21,43.657 ; v1(9.224,43.671) 9.923,43.671 9.934,43.66 ; 20.658,43.755 20.671,43.742 24.131,43.742 24.159,43.714 ; 22.775,22.306 29.608,22.306 29.647,22.267 30.63,22.267 30.65,22.287 30.65,32.37 ; 30.05,43.742 30.063,43.755 30.658,43.755 ; 30.63,18.295 30.658,18.267 ; 30.65,40.742 30.658,40.75 30.658,43.742 ; 30.658,32.37 30.658,34.928
  other v1: 4.894,0.508 6.723,0.508 8.527,0.508 10.228,0.508 11.93,0.508 13.607,0.508 19.017,0.508 20.261,0.508 21.608,0.508 22.776,0.508 24.046,0.508 25.341,0.508 26.978,0.508 28.516,0.508 30.193,0.508 31.916,0.508 34.028,0.508 36.06,0.508 37.61,0.508 39.024,0.508 40.454,0.508 3.04,0.533 15.588,0.533 17.467,0.533 41.521,0.559 1.567,0.584 29.085,1.27 31.213,1.27 27.707,1.346 42.436,1.337 0.546,1.362 1.85,1.431 3.497,1.437 6.65,1.431 7.85,1.431 13.85,1.431 16.25,1.431 33.05,1.431 36.65,1.431 39.05,1.431 41.45,1.431 5.631,1.473 35.628,1.575 14.597,1.651 17.264,1.651 37.838,1.702 34.319,1.716 40.607,1.716 5.352,2.327 7.206,2.327 15.98,2.464 0.526,2.489 2.507,2.478 4.284,2.478 42.486,2.565 13.25,2.631 14.45,2.631 17.264,2.972 28.034,2.972 28.819,3.308 15.588,3.483 38.899,3.554 4.229,3.634 42.467,3.761 0.526,3.81 29.45,3.831 27.844,4.181 33.941,4.204 28.645,4.356 16.371,4.547 17.364,4.547 31.88,4.571 22.141,4.588 23.03,4.579 31.25,5.031 29.25,5.072 0.5,5.215 42.486,5.225 16.607,5.337 9.05,6.231 38.631,6.285 34.028,6.532 4.331,6.62 42.461,6.655 14.99,6.863 12.388,7.012 39.078,7.509 42.461,7.645 0.5,7.735 33.494,7.804 4.372,7.865 16.444,8.148 11.205,8.354 12.762,8.354 8.947,8.388 18.507,8.584 15.319,8.589 14.232,8.704 42.486,8.998 0.5,9.04 16.518,9.04 15.897,9.482 16.861,9.482 18.501,9.482 8.37,9.687 9.716,9.687 11.205,9.687 14.936,9.687 13.89,9.778 0.551,10.453 42.461,10.475 14.449,10.501 27.285,10.74 4.306,10.75 38.598,10.918 0.576,11.395 42.461,11.43 8.999,11.573 34.319,11.573 4.306,11.725 23.371,12.048 38.494,12.182 18.174,12.24 25.362,12.441 14.915,12.776 16.299,12.794 42.486,12.791 0.5,12.85 11.059,13.025 38.505,13.58 0.526,14.3 42.41,14.3 34.678,14.773 38.494,14.776 4.331,14.824 20.853,14.824 22.642,14.824 18.359,14.879 16.299,14.893 32.23,14.893 0.576,15.189 42.385,15.189 30.398,15.381 38.493,16.09 26.309,16.358 4.372,16.45 0.5,16.615 13.868,16.63 42.486,16.615 30.398,16.944 28.234,16.975 29.132,17.013 4.356,17.39 18.203,17.413 19.662,17.407 16.247,17.452 38.522,17.514 33.998,17.697 0.5,18.085 42.436,18.074 4.331,18.482 38.566,18.589 42.461,19.013 0.526,19.05 33.283,19.4 38.598,19.6 19.61,19.692 12.432,19.716 18.099,19.727 21.084,19.727 24.191,19.727 14.659,19.755 16.432,19.755 22.309,19.755 25.218,19.771 4.382,19.828 42.486,20.454 8.166,21.045 4.372,21.098 24.587,21.43 21.419,21.457 18.081,21.557 38.621,21.666 0.5,21.71 42.436,21.869 4.382,22.266 34.481,22.721 38.621,22.721 42.436,22.871 0.526,23.165 13.607,23.188 21.875,23.352 4.382,23.409 19.526,23.726 34.684,23.734 0.5,24.106 21.768,24.233 42.486,24.238 4.407,24.476 0.5,25.531 26.127,25.569 42.461,25.659 13.574,25.824 38.631,26.079 8.268,26.194 24.071,26.337 42.436,26.617 0.5,26.82 26.051,27.421 4.407,27.448 24.101,27.448 42.486,28.068 0.5,28.103 4.407,28.286 26.054,28.457 38.631,29.355 0.551,29.464 9.224,29.464 42.436,29.515 4.331,30.013 10.207,30.01 19.526,30.14 20.324,30.14 21.072,30.14 21.875,30.14 22.58,30.14 38.82,30.339 42.467,30.404 0.576,30.476 20.308,30.856 19.526,30.894 21.053,30.894 21.875,30.894 22.533,30.894 9.185,31.013 4.356,31.258 8.45,31.431 42.486,31.848 0.5,31.891 9.185,32.113 19.514,32.388 21.053,32.388 21.971,32.388 4.331,32.579 8.935,32.904 21.072,33.087 21.875,33.087 22.533,33.087 19.431,33.153 12.946,33.19 27.222,33.19 42.436,33.341 0.551,33.417 17.285,33.544 4.356,33.798 31.25,33.831 38.67,33.843 13.145,33.976 18.53,34.027 17.006,34.204 42.467,34.38 36.589,34.668 38.351,34.697 0.521,34.733 2.1,34.759 39.066,34.759 40.556,34.773 3.163,34.789 4.356,34.789 5.855,34.814 7.684,34.835 15.978,34.852 41.45,35.031 35.711,35.343 14.948,35.424 18.784,35.474 37.12,35.627 16.984,35.642 8.166,35.728 11.9,35.728 32.358,35.72 12.967,35.779 14.059,35.805 42.486,35.832 0.526,35.906 2.71,35.982 4.894,35.982 6.825,36.023 39.083,36.068 3.65,36.231 6.05,36.231 38.45,36.231 40.581,36.236 9.21,36.556 36.122,36.673 20.312,36.751 11.355,36.928 13.635,36.928 14.761,36.928 15.749,36.928 18.798,36.928 22.198,36.928 37.338,36.928 0.551,37.135 12.432,37.135 42.477,37.236 10.228,37.27 39.184,37.313 2.027,37.324 3.878,37.363 5.936,37.363 3.05,37.431 7.85,37.431 16.299,37.44 21.05,37.431 36.65,37.431 40.25,37.431 41.45,37.431 18.65,37.597 38.036,37.597 9.21,37.719 20.277,37.719 13.134,37.795 10.944,37.998 40.632,38.01 36.122,38.047 13.962,38.311 16.904,38.311 21.355,38.311 24.955,38.311 26.775,38.311 28.729,38.311 30.658,38.311 0.551,38.456 12.637,38.456 15.978,38.456 18.76,38.456 3.65,38.631 6.05,38.631 8.45,38.631 24.05,38.631 27.65,38.631 20.308,38.71 10.178,38.786 2.735,38.837 37.812,38.837 42.461,38.837 4.869,38.862 6.85,38.862 15.283,38.887 36.762,38.887 39.449,38.993 11.753,39.065 13.962,39.116 22.312,39.173 18.798,39.236 40.962,39.236 16.912,39.345 34.101,39.345 35.325,39.6 0.551,39.675 26.054,39.74 27.274,39.74 30.04,39.743 28.792,39.752 25.172,39.782 20.211,39.827 37.338,39.827 6.65,39.831 7.85,39.831 9.05,39.831 10.25,39.831 11.45,39.831 12.65,39.831 13.85,39.831 21.05,39.831 23.45,39.831 31.85,39.831 39.05,39.831 15.308,39.878 32.894,39.878 16.324,39.919 36.122,39.919 40.505,40.437 38.522,40.462 1.821,40.488 2.659,40.488 4.031,40.488 5.504,40.488 6.85,40.488 8.192,40.488 10.66,40.488 32.23,40.488 34.308,40.488 22.263,40.615 11.498,40.64 19.645,40.64 24.071,40.64 12.184,40.691 20.314,40.691 13.454,40.716 15.305,40.716 15.978,40.716 0.576,40.724 17.112,40.742 33.212,40.742 35.288,40.97 36.624,40.97 42.467,40.97 4.85,41.031 9.65,41.031 14.45,41.031 21.65,41.031 25.25,41.031 26.45,41.031 27.65,41.031 28.85,41.031 30.05,41.031 31.25,41.031 39.65,41.031 17.055,41.456 18.65,41.456 0.576,41.639 20.206,41.639 15.371,41.664 3.175,41.838 5.191,41.838 7.208,41.838 11.202,41.842 42.467,41.927 25.209,42.023 27.309,42.056 29.41,42.056 31.51,42.056 33.611,42.056 17.057,42.076 18.589,42.076 35.711,42.064 37.812,42.076 39.912,42.076 9.05,42.231 13.85,42.231 16.25,42.231 21.05,42.231 22.25,42.231 23.45,42.231 28.25,42.231 30.65,42.231 36.65,42.231 39.05,42.231 41.45,42.231 0.576,42.426 20.206,42.596 15.371,42.621 12.256,42.627 2.167,42.755 4.183,42.755 6.2,42.755 8.216,42.755 10.232,42.754 17.175,42.81 42.467,42.918 26.259,42.96 28.36,42.972 32.561,42.972 34.661,42.96 36.762,42.993 38.862,42.993 40.962,42.993 24.159,43.023 18.547,43.155 0.576,43.315 16.85,43.431 19.25,43.431 21.65,43.431 22.85,43.431 20.206,43.586 15.371,43.612 3.175,43.671 5.191,43.671 7.208,43.671 11.24,43.671 42.467,43.807 25.209,43.857 27.309,43.889 29.41,43.889 31.51,43.889 33.611,43.889 35.711,43.897 37.812,43.909 39.912,43.909 17.112,43.992 0.576,44.475 20.206,44.475 15.371,44.501 2.167,44.588 4.183,44.588 6.2,44.588 8.216,44.588 10.232,44.588 12.172,44.598 42.467,44.594 3.05,44.631 5.45,44.631 9.05,44.631 11.45,44.631 13.85,44.631 16.25,44.631 18.65,44.631 21.05,44.631 22.25,44.631 23.45,44.631 29.45,44.631 31.85,44.631 40.25,44.631 26.259,44.793 28.36,44.806 30.46,44.806 32.561,44.806 34.661,44.794 36.762,44.826 38.862,44.826 40.962,44.826 24.159,44.902 17.157,45.076 20.206,45.263 0.5,45.288 15.371,45.288 18.57,45.509 42.467,45.509 1.25,45.831 2.45,45.831 3.65,45.831 4.85,45.831 6.05,45.831 7.25,45.831 8.45,45.831 9.65,45.831 10.85,45.831 12.05,45.831 13.25,45.831 14.45,45.831 16.85,45.831 19.25,45.831 21.65,45.831 22.85,45.831 24.05,45.831 25.25,45.831 26.45,45.831 27.65,45.831 28.85,45.831 30.05,45.831 31.25,45.831 32.45,45.831 33.65,45.831 34.85,45.831 36.05,45.831 37.25,45.831 38.45,45.831 39.65,45.831 40.85,45.831 0.5,46.177 15.305,46.177 18.533,46.177 20.219,46.177 42.477,46.604 17.112,46.637 0.5,46.99 1.85,47.031 3.05,47.031 4.25,47.031 5.45,47.031 6.65,47.031 7.85,47.031 9.05,47.031 10.25,47.031 11.45,47.031 16.25,47.031 18.65,47.031 24.65,47.031 25.85,47.031 27.05,47.031 28.25,47.031 29.45,47.031 30.65,47.031 31.85,47.031 33.05,47.031 34.25,47.031 35.45,47.031 36.65,47.031 37.85,47.031 39.05,47.031 40.25,47.031 41.45,47.031 42.461,47.498 17.149,47.752 0.5,48.006 18.547,48.006 2.45,48.231 3.65,48.231 4.85,48.231 6.05,48.231 7.25,48.231 8.45,48.231 9.65,48.231 10.85,48.231 16.85,48.231 19.25,48.231 20.45,48.231 24.05,48.231 25.25,48.231 26.45,48.231 27.65,48.231 28.85,48.231 30.05,48.231 31.25,48.231 32.45,48.231 33.65,48.231 34.85,48.231 36.05,48.231 37.25,48.231 38.45,48.231 39.65,48.231 40.85,48.231 42.461,48.26 0.5,49.022 42.461,49.022 1.85,49.431 3.05,49.431 4.25,49.431 5.45,49.431 6.65,49.431 7.85,49.431 9.05,49.431 10.25,49.431 11.45,49.431 16.25,49.431 18.65,49.431 24.65,49.431 25.85,49.431 27.05,49.431 28.25,49.431 29.45,49.431 30.65,49.431 31.85,49.431 33.05,49.431 34.25,49.431 35.45,49.431 36.65,49.431 37.85,49.431 39.05,49.431 40.25,49.431 41.45,49.431 42.477,49.76 0.5,50.038 42.461,50.546 1.25,50.631 2.45,50.631 3.65,50.631 4.85,50.631 6.05,50.631 7.25,50.631 8.45,50.631 9.65,50.631 10.85,50.631 16.85,50.631 19.25,50.631 20.45,50.631 24.05,50.631 25.25,50.631 26.45,50.631 27.65,50.631 28.85,50.631 30.05,50.631 31.25,50.631 32.45,50.631 33.65,50.631 34.85,50.631 36.05,50.631 37.25,50.631 38.45,50.631 39.65,50.631 40.85,50.631 0.5,51.05 42.164,51.308 41.656,51.692 16.25,51.831 30.226,52.093 31.142,52.093 32.058,52.093 32.974,52.093 33.89,52.093 34.806,52.093 35.722,52.093 36.638,52.093 37.554,52.093 38.47,52.093 39.386,52.093 40.302,52.093 1.835,52.137 2.747,52.134 20.741,52.123 21.489,52.123 22.586,52.123 23.699,52.123 24.729,52.123 25.645,52.123 26.561,52.123 27.478,52.123 28.394,52.123 29.31,52.123 3.662,52.16 4.578,52.176 5.493,52.202 6.406,52.199 7.319,52.204 8.237,52.207 9.125,52.2 10.041,52.2 11.027,52.2 12.087,52.2 13.448,52.2 14.312,52.2 41.277,52.229
GPIO3/BOOT0: CN1.9 R1.1 U1.22 | length 28
  Top Layer w0.2: v1(10.388,31.593) 10.838,31.143 10.838,30.628 R1.1@10.882,30.583 ; U1.22@20.264,34 20.264,35.862 v1(20.308,35.906) ; v1@20.295,35.753 20.33,35.789 v1@20.33,35.837
  Internal 1 w0.2: v1(10.3,36.394) 10.3,36.311 10.066,36.076 10.066,35.566 10.066,31.915 v1(10.388,31.593)
  Bottom Layer w0.2: CN1.9@2.334,28.708 4.052,28.708 4.703,29.36 8.199,29.36 9.246,30.407 9.673,30.407 10.388,31.122 v1(10.388,31.593) ; v1(10.3,36.394) 10.316,36.378 19.836,36.378 v1(20.308,35.906)
GPIO4: CN1.10 SB32.2 | length 33.4
  Internal 1 w0.2: v1(9.938,19.755) 9.182,20.511 9.182,27.986 9.753,28.557 10.051,28.557 10.387,28.893 v1(10.496,28.893)
  Bottom Layer w0.2: CN1.10@6.398,28.708 9.797,28.708 9.904,28.816 10.419,28.816 v1(10.496,28.893) ; v1(9.938,19.755) 11.693,19.755 12.377,20.44 21.964,20.44 21.988,20.416 26.938,20.416 27.753,19.6 SB32.2@28.294,19.6
GPIO5/JTMS/SWDIO: CN1.13 R2.2 SB28.2 U1.19 | length 79.7
  Top Layer w0.2: U1.19@21.764,34 21.764,34.837 22.533,35.606 v1(22.533,35.656)
  Internal 1 w0.2: v1(16.518,10.927) 16.951,11.36 16.951,16.69 17.151,16.89 17.151,23.006 v1(16.747,23.409) ; v1(30.193,20.283) 30.178,20.298 30.178,20.716 30.1,20.794 30.1,21.369 31.487,22.757 31.487,31.17 31.784,31.466 31.784,31.781 32.908,32.906 32.908,37.069 v1(32.843,37.135)
  Bottom Layer w0.2: CN1.13@2.334,26.168 4.067,26.168 4.726,26.827 4.891,26.827 4.898,26.82 7.899,26.82 8.096,27.017 10.883,27.017 14.282,23.618 16.431,23.618 16.639,23.409 v1(16.747,23.409) 17.851,22.306 28.379,22.306 30.116,20.569 30.116,20.359 v1(30.193,20.283) ; v1(16.518,10.927) 16.604,10.927 16.835,11.157 19.226,11.157 19.565,10.818 19.565,10.368 R2.2@19.605,10.328 ; v1(22.533,35.656) 22.609,35.733 22.609,36.023 23.809,37.223 32.526,37.223 32.537,37.211 32.766,37.211 v1(32.843,37.135) ; v1@32.048,31.938 32.465,31.938 SB28.2@32.475,31.948 ; SB28.2@32.481,31.942 32.485,31.938 32.485,31.722
  Bottom Layer w0.21: SB28.2@32.475,31.948 SB28.2@32.481,31.942
  other v1: 31.85,31.848
GPIO6/JTCK/SWCLK: CN1.15 R3.2 SB42.2 U1.18 | length 74.7
  Top Layer w0.2: U1.18@22.264,34 22.283,34.019 22.283,34.378 23.973,36.068 24.92,36.068 v1(24.954,36.034)
  Internal 1 w0.2: v1(15.588,10.166) v1(15.588,21.022) ; v1(24.954,36.034) 24.954,34.428 24.2,33.674 24.2,31.814 25.204,30.81 25.204,25.584 26.127,24.66 26.127,22.232 25.922,22.027 v1(25.922,21.022)
  Internal 2 w0.21: v1(15.588,10.166) 19.734,10.166 v1(20.964,11.395)
  Bottom Layer w0.2: CN1.15@2.334,24.898 3.991,24.898 4.636,25.543 11.073,25.543 11.084,25.553 11.851,25.553 12.148,25.257 12.148,22.981 14.108,21.022 v1(15.588,21.022) ; v1@15.63,21.064 15.905,20.79 22.109,20.79 22.133,20.766 25.605,20.766 25.861,21.022 v1(25.922,21.022) ; R3.2@20.887,10.328 20.887,11.213 20.964,11.29 v1(20.964,11.395) ; v1(24.954,36.034) 25.401,35.587 31.714,35.587 32.453,34.848 SB42.2@32.453,33.202
GPIO11: CN1.24 SB11.1 | length 5.5
  Bottom Layer w0.2: CN1.24@6.398,19.818 8.449,19.818 9.369,18.898 11.466,18.898 11.472,18.893 11.531,18.893 SB11.1@11.541,18.883
GPIO12: CN1.26 SB14.1 | length 5.4
  Bottom Layer w0.2: CN1.26@6.398,18.548 10.847,18.548 11.113,18.283 11.14,18.283 SB14.1@11.541,17.882
GPIO15/OSC32_IN: CN1.33 SB37.2 | length 44.5
  Internal 1 w0.2: v1(27.274,14.3) 27.274,21.718 27.459,21.903 27.459,24.368 27.027,24.8 27.027,28.98 28.564,30.516 28.564,31.947 28.388,32.123 28.113,32.123 v1(28.038,32.198)
  Bottom Layer w0.2: CN1.33@2.334,13.468 4.279,13.468 4.931,14.12 18.185,14.12 18.34,14.274 27.248,14.274 v1(27.274,14.3)
GPIO16/OSC32_OUT: CN1.35 SB38.2 | length 44.9
  Internal 1 w0.2: v1(18.321,13.1) 19.238,12.182 21.307,12.182 21.971,12.847 21.971,15.965 21.602,16.334 21.602,17.205 v1(21.626,17.229) ; v1(26.063,17.239) 26.051,17.251 26.051,20.373 26.504,20.825 26.504,25.167 26.677,25.341 26.677,29.125 26.978,29.425 26.978,29.428 27.983,30.434 27.983,30.831 v1(28.009,30.856)
  Bottom Layer w0.2: CN1.35@2.334,12.198 3.966,12.198 4.617,12.85 8.413,12.85 9.277,13.714 17.891,13.714 18.032,13.572 18.032,13.497 18.321,13.208 v1(18.321,13.1) ; v1(21.626,17.229) 23.456,17.229 23.481,17.255 25.465,17.255 25.48,17.239 v1(26.063,17.239) ; v1(28.009,30.856) v1@28.11,30.755
GPIO17: CN1.36 SB15.1 | length 4.1
  Bottom Layer w0.2: CN1.36@6.398,12.198 6.461,12.136 10.432,12.136 10.437,12.14 10.457,12.14 SB15.1@10.462,12.136
GPIO18: CN1.38 SB23.1 | length 4.1
  Bottom Layer w0.2: CN1.38@6.398,10.928 10.43,10.928 10.499,10.86 SB23.1@10.505,10.86
GPIO21: CN1.42 SB29.2 | length 9.6
  Internal 1 w0.2: v1(11.539,7.645) 11.525,7.632 11.525,5.463 12.04,4.948 12.04,4.843 v1(12.146,4.843)
  Bottom Layer w0.2: CN1.42@6.398,8.388 8.169,8.388 8.753,7.804 11.272,7.804 11.431,7.645 v1(11.539,7.645) ; v1(12.146,4.843) 12.596,5.293 SB29.2@12.975,5.293
GPIO22: CN1.44 SB30.1 | length 2.3
  Bottom Layer w0.2: CN1.44@6.398,7.118 SB30.1@8.708,7.118
GPIO23: CN1.45 R9.1 SB27.1 | length 28.2
  Bottom Layer w0.2: CN1.45@2.334,5.848 3.956,5.848 4.574,5.23 11.338,5.23 12.393,6.285 15.745,6.285 15.748,6.282 16.366,6.282 16.369,6.285 25.957,6.285 27.024,5.218 ; R9.1@27.024,4.8 27.024,5.218 ; SB27.1@27.663,6.648 27.181,6.648 27.024,6.49 27.024,5.218
GPIO24: CN1.47 R8.2 SB20.1 | length 32.2
  Internal 1 w0.2: v1(13.421,3.9) 13.498,3.976 13.498,4.19 13.525,4.217 13.525,7.5 v1(13.5,7.525)
  Bottom Layer w0.2: CN1.47@2.334,4.578 4.102,4.578 4.712,3.969 4.889,3.969 4.898,3.96 7.899,3.96 7.908,3.969 SB20.1@8.774,3.969 8.774,3.954 9.011,3.717 9.011,3.515 9.158,3.369 12.89,3.369 v1(13.421,3.9) v1@13.369,3.952 ; v1(13.5,7.525) 26.61,7.525 26.632,7.547 26.632,10.049 26.353,10.328 R8.2@25.922,10.328
GPIO25: CN2.4 SB42.1 | length 7.6
  Bottom Layer w0.2: SB42.1@33.391,33.153 33.401,33.142 33.44,33.142 33.445,33.137 38.125,33.137 38.743,32.518 CN2.4@40.688,32.518
GPIO26: CN2.5 U1.9 | length 14.6
  Top Layer w0.2: U1.9@23.458,29.825 23.458,29.43 v1(23.77,29.118)
  Internal 2 w0.2: v1(23.77,29.118) 27.661,29.118 28.727,30.183 32.901,30.183 v1(33.847,31.129)
  Bottom Layer w0.2: v1(33.847,31.129) 34.447,31.129 34.566,31.248 CN2.5@36.624,31.248
GPIO27: CN2.6 SB28.1 | length 7.5
  Bottom Layer w0.2: SB28.1@33.44,31.948 33.515,31.873 38.198,31.873 38.823,31.248 CN2.6@40.688,31.248
GPIO28: CN2.7 SB33.1 | length 3.8
  Bottom Layer w0.2: SB33.1@32.923,30.183 32.923,30.168 32.998,30.093 32.998,30.064 36.539,30.064 CN2.7@36.624,29.978
GPIO29: CN2.9 SB7.2 | length 6.5
  Bottom Layer w0.2: SB7.2@30.632,29.887 31.021,29.887 31.958,28.95 36.383,28.95 CN2.9@36.624,28.708
GPIO30: CN2.10 SB31.2 | length 16.9
  Internal 1 w0.2: v1(32.534,20.267) 33.437,21.171 33.437,26.282 33.95,26.794 33.95,28.281 v1(33.998,28.33)
  Bottom Layer w0.2: 32.406,19.253 32.505,19.351 32.505,19.508 32.521,19.525 32.521,20.255 v1(32.534,20.267) ; v1(33.998,28.33) 34.512,28.33 34.752,28.09 38.603,28.09 v1@38.616,28.103 ; v1(38.672,28.159) v1@38.616,28.103 ; CN2.10@40.688,28.708 39.221,28.708 v1@38.616,28.103
GPIO31: CN2.11 SB26.1 | length 6.5
  Bottom Layer w0.2: SB26.1@30.45,28.09 31.017,28.09 31.684,27.423 34.497,27.423 34.498,27.421 36.607,27.421 CN2.11@36.624,27.438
